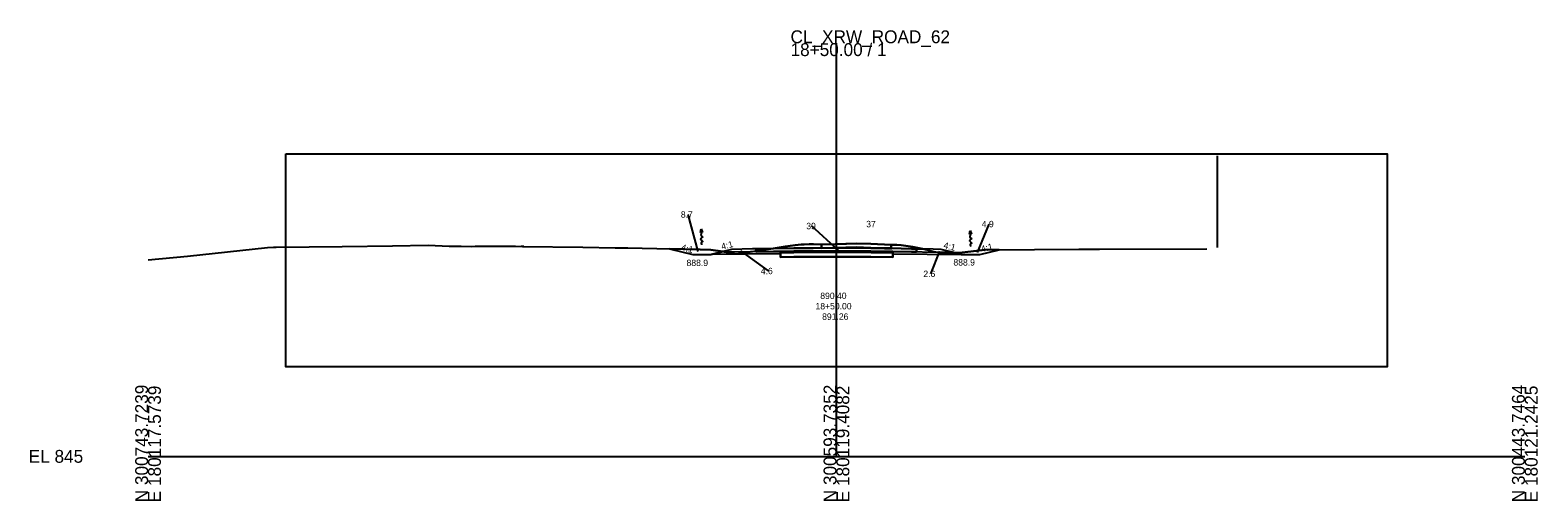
# Model space of a CAD drawing. Extents: x -26 to 180171, y 490 to 300744.
# Drawn here: x -25.7 to 302.8, y 3490.3 to 3592.8 of the extents above; entities that cross this region are included whole.
import ezdxf

# ---------------------------------------------------------------- set-up
doc = ezdxf.new("R2010")
doc.units = 0
for name, color, linetype in [('CM_Corridor_Top_Mesh', 7, 'Continuous'), ('Default', 7, 'Continuous'), ('DR_P_Ditch', 7, 'Continuous'), ('DT_P_Contour_Major', 7, 'Continuous'), ('DT_P_Spot_Elevations', 7, 'Continuous'), ('DT_P_TIN_Hull', 7, 'Continuous'), ('DT_P_Void', 7, 'Continuous'), ('DT_X_Void', 7, 'Continuous'), ('GK_Patterns', 7, 'Continuous'), ('MD_P_Surface_Aggregate_Base', 7, 'Continuous'), ('MD_P_Surface_Asphalt_Concrete_Base', 7, 'Continuous'), ('MD_P_Surface_Asphalt_Concrete_Surface_Course', 7, 'Continuous'), ('MD_P_Surface_Chemically_Stabalized_Subgrade', 7, 'Continuous'), ('PV_P_Saw_Cut_Line', 7, 'Continuous'), ('RD_P_Fence', 7, 'Continuous'), ('RW_P_Const_Limits', 7, 'Continuous'), ('RW_P_Esmt_LA', 7, 'Continuous'), ('RW_X_CL_50', 7, 'Continuous'), ('SC_Scratch1', 7, 'Continuous'), ('SV_X_Control_Cells_Found', 7, 'Continuous'), ('SV_X_Text_Name', 7, 'Continuous'), ('TX_P_1', 7, 'Continuous'), ('XS_X_Ground_Line', 7, 'Continuous')]:
    doc.layers.add(name, color=color, linetype=linetype)

msp = doc.modelspace()

# ---------------------------------------------------------------- linework, layer by layer
at = {"layer": 'CM_Corridor_Top_Mesh'}
for p, q in [((118.69, 3543.96), (122.69, 3543.96)), ((177.25, 3543.96), (181.25, 3543.96))]:
    msp.add_line(p, q, dxfattribs=at)
at = {"layer": 'DR_P_Ditch'}
msp.add_lwpolyline([(167.48, 3545.22), (167.48, 3544.55), (166.36, 3544.58), (161.86, 3544.65), (157.53, 3544.7), (153.32, 3544.73), (149.14, 3544.73), (144.96, 3544.72), (140.71, 3544.68), (136.32, 3544.62), (132.5, 3544.55), (132.5, 3545.22), (136.32, 3545.29), (140.71, 3545.35), (144.96, 3545.38), (149.14, 3545.4), (153.32, 3545.39), (157.53, 3545.37), (161.86, 3545.32), (166.36, 3545.24), (167.48, 3545.22)], dxfattribs=at)
at = {"layer": 'DT_P_Contour_Major'}
for points in [[(132.5, 3544.55), (132.5, 3545.22)], [(167.48, 3544.55), (167.48, 3545.22)], [(167.48, 3544.55), (166.36, 3544.58), (162.28, 3544.64), (162.28, 3543.4), (161.86, 3543.41), (157.53, 3543.44), (153.32, 3543.46), (149.14, 3543.46), (144.96, 3543.45), (140.71, 3543.43), (137.83, 3543.4), (137.83, 3544.64), (136.32, 3544.62), (132.5, 3544.55)]]:
    msp.add_lwpolyline(points, dxfattribs=at)
at = {"layer": 'DT_P_Spot_Elevations'}
msp.add_lwpolyline([(172.81, 3545.06), (171.11, 3545.12), (167.48, 3545.22), (167.48, 3544.55), (166.36, 3544.58), (162.28, 3544.64), (161.86, 3544.65), (157.53, 3544.7), (153.32, 3544.73), (149.14, 3544.73), (144.96, 3544.72), (140.71, 3544.68), (137.83, 3544.64), (136.32, 3544.62), (132.5, 3544.55), (132.5, 3545.22), (131.72, 3545.2), (127.11, 3545.06)], dxfattribs=at)
at = {"layer": 'DT_P_Void'}
msp.add_lwpolyline([(30, 3565.91), (270, 3565.91), (270, 3519.48), (30, 3519.48)], close=True, dxfattribs=at)
at = {"layer": 'DT_X_Void'}
for p, q in [((150, 3500), (150, 3590)), ((0, 3500), (150, 3500)), ((150, 3500), (300, 3500))]:
    msp.add_line(p, q, dxfattribs=at)
at = {"layer": 'GK_Patterns'}
for p, q in [((113.65, 3545.22), (118.69, 3543.96)), ((127.11, 3545.06), (122.69, 3543.96)), ((177.25, 3543.96), (172.81, 3545.06)), ((181.25, 3543.96), (185.46, 3545.01))]:
    msp.add_line(p, q, dxfattribs=at)
at = {"layer": 'MD_P_Surface_Asphalt_Concrete_Base'}
msp.add_lwpolyline([(146.78, 3546.17), (146.78, 3545.32), (149.72, 3545.39), (154.39, 3545.55), (157.5, 3545.43), (161.92, 3545.23), (161.92, 3546.09), (157.5, 3546.28), (154.39, 3546.4), (149.72, 3546.25), (146.78, 3546.17)], dxfattribs=at)
at = {"layer": 'MD_P_Surface_Asphalt_Concrete_Surface_Course'}
for p, q in [((120.35, 3548.78), (120.55, 3549.59)), ((120.78, 3548.79), (120.35, 3548.78)), ((120.55, 3549.59), (120.78, 3548.79)), ((178.97, 3548.42), (179.17, 3549.22)), ((179.4, 3548.43), (178.97, 3548.42)), ((179.17, 3549.22), (179.4, 3548.43))]:
    msp.add_line(p, q, dxfattribs=at)
for points in [[(120.56, 3548.79), (120.56, 3548.76), (120.49, 3548.43), (120.43, 3548.22), (120.8, 3547.8), (120.4, 3547.31), (120.83, 3546.76), (120.61, 3546.64), (120.63, 3546.09)], [(179.18, 3548.42), (179.18, 3548.39), (179.12, 3548.06), (179.05, 3547.85), (179.42, 3547.44), (179.02, 3546.94), (179.45, 3546.39), (179.23, 3546.27), (179.25, 3545.72)]]:
    msp.add_spline(points, degree=3, dxfattribs=at)
at = {"layer": 'MD_P_Surface_Chemically_Stabalized_Subgrade'}
for p, q in [((137.83, 3544.4), (137.83, 3543.4)), ((137.83, 3543.4), (140.71, 3543.43)), ((162.28, 3543.4), (162.28, 3544.4))]:
    msp.add_line(p, q, dxfattribs=at)
for points in [[(162.28, 3544.4), (161.86, 3544.41), (157.53, 3544.44), (153.32, 3544.46), (149.14, 3544.46), (144.96, 3544.45), (140.71, 3544.43), (137.83, 3544.4)], [(140.71, 3543.43), (144.96, 3543.45), (149.14, 3543.46), (153.31, 3543.46), (157.53, 3543.44), (162.28, 3543.4)]]:
    msp.add_lwpolyline(points, dxfattribs=at)
at = {"layer": 'PV_P_Saw_Cut_Line'}
msp.add_lwpolyline([(172.81, 3545.06), (171.11, 3545.12), (167.48, 3545.22), (166.36, 3545.24), (161.86, 3545.32), (157.53, 3545.37), (153.32, 3545.39), (149.14, 3545.4), (144.96, 3545.38), (140.71, 3545.35), (136.32, 3545.29), (132.5, 3545.22), (131.72, 3545.2), (127.11, 3545.06)], dxfattribs=at)
at = {"layer": 'RD_P_Fence'}
msp.add_lwpolyline([(146.78, 3546.17), (146.78, 3545.32), (149.72, 3545.39), (154.39, 3545.55), (157.5, 3545.43), (161.92, 3545.23), (161.92, 3546.09), (157.5, 3546.28), (154.39, 3546.4), (149.72, 3546.25), (146.78, 3546.17)], dxfattribs=at)
at = {"layer": 'RW_P_Const_Limits'}
for points in [[(132.5, 3545.22), (131.72, 3545.2), (127.11, 3545.06)], [(172.81, 3545.06), (171.11, 3545.12), (167.48, 3545.22)]]:
    msp.add_lwpolyline(points, dxfattribs=at)
at = {"layer": 'RW_P_Esmt_LA'}
msp.add_lwpolyline([(146.78, 3546.17), (149.72, 3546.25), (154.39, 3546.4), (157.5, 3546.28), (161.92, 3546.09)], dxfattribs=at)
at = {"layer": 'RW_X_CL_50'}
for points in [[(27.65, 3545.52), (27.35, 3545.52)], [(81.61, 3545.73), (81.31, 3545.73)]]:
    msp.add_lwpolyline(points, dxfattribs=at)
at = {"layer": 'SC_Scratch1'}
msp.add_lwpolyline([(0, 3542.82), (8.6, 3543.64), (26.04, 3545.52), (27.92, 3545.55), (42.32, 3545.7), (53.24, 3545.84), (61.07, 3546), (65.62, 3545.76), (68.23, 3545.75), (70.4, 3545.71), (71.31, 3545.79), (77.06, 3545.78), (80.04, 3545.78), (81.62, 3545.74), (94.74, 3545.56), (101.79, 3545.43), (104.57, 3545.4), (120.33, 3545.08), (122.64, 3544.97), (123.62, 3544.83), (124.26, 3544.78), (128.18, 3544.15), (136.19, 3545.3), (138.83, 3545.7), (141.03, 3545.98), (142.33, 3546.15), (143, 3546.18), (144.03, 3546.24), (145, 3546.22), (146.78, 3546.17), (150, 3546.25), (154.39, 3546.4), (157.5, 3546.28), (161.92, 3546.09), (163.19, 3546.06), (164.1, 3546.04), (166.65, 3545.63), (168.11, 3545.34), (171.22, 3544.66), (172.78, 3544.3), (174.17, 3544.33), (176.72, 3544.3), (179.3, 3544.6), (182.36, 3545), (193.19, 3545.04), (202.81, 3545.16), (207.32, 3545.13), (230.71, 3545.2)], dxfattribs=at)
at = {"layer": 'SV_X_Control_Cells_Found'}
msp.add_line((232.96, 3565.49), (232.96, 3545.49), dxfattribs=at)
at = {"layer": 'SV_X_Text_Name'}
for p, q in [((119.87, 3544.59), (117.72, 3552.69)), ((150.42, 3544.81), (144.58, 3550.18)), ((180.73, 3544.44), (183.27, 3550.6)), ((113.65, 3545.22), (118.69, 3543.96)), ((127.11, 3545.06), (125.31, 3544.61)), ((132.5, 3544.77), (132.5, 3545.22)), ((146.78, 3545.32), (146.78, 3546.17)), ((149.72, 3545.39), (146.78, 3545.32)), ((154.39, 3545.55), (149.72, 3545.39)), ((157.5, 3545.43), (154.39, 3545.55)), ((167.48, 3544.55), (167.48, 3545.22)), ((167.48, 3545.22), (168.84, 3545.18)), ((168.84, 3545.18), (168.11, 3545.34)), ((168.84, 3545.18), (171.22, 3544.66)), ((175.84, 3544.31), (172.81, 3545.06)), ((181.25, 3543.96), (185.46, 3545.01)), ((185.46, 3545.01), (182.36, 3545)), ((118.69, 3543.96), (122.69, 3543.96)), ((122.69, 3543.96), (125.31, 3544.61)), ((125.31, 3544.61), (124.26, 3544.78)), ((125.31, 3544.61), (128.18, 3544.15)), ((128.18, 3544.15), (132.5, 3544.77)), ((129.09, 3544.74), (135.13, 3540.38)), ((132.5, 3544.77), (132.5, 3544.55)), ((172.48, 3544.73), (170.53, 3539.76)), ((175.84, 3544.31), (177.25, 3543.96)), ((177.25, 3543.96), (181.25, 3543.96))]:
    msp.add_line(p, q, dxfattribs=at)
for points in [[(124.26, 3544.78), (123.62, 3544.83), (122.64, 3544.97), (120.33, 3545.08), (113.65, 3545.22)], [(132.5, 3545.22), (131.72, 3545.2), (127.11, 3545.06)], [(146.78, 3546.17), (145, 3546.22), (144.03, 3546.24), (143, 3546.18), (142.33, 3546.15), (141.03, 3545.98), (138.83, 3545.7), (136.19, 3545.3), (132.5, 3544.77)], [(161.92, 3546.09), (161.92, 3545.23), (157.5, 3545.43)], [(168.11, 3545.34), (166.65, 3545.63), (164.1, 3546.04), (163.19, 3546.06), (161.92, 3546.09)], [(172.81, 3545.06), (171.11, 3545.12), (168.84, 3545.18)], [(182.36, 3545), (179.3, 3544.6), (176.72, 3544.3), (175.84, 3544.31)], [(132.5, 3544.55), (136.32, 3544.62), (137.83, 3544.64), (137.83, 3544.4), (140.7, 3544.44), (145.02, 3544.45), (149.14, 3544.5), (153.46, 3544.46)], [(153.46, 3544.46), (157.54, 3544.44), (161.39, 3544.41), (162.28, 3544.4)], [(162.28, 3544.4), (162.28, 3544.64), (166.36, 3544.58), (167.48, 3544.55)], [(171.22, 3544.66), (172.78, 3544.3), (174.17, 3544.33), (175.84, 3544.31)]]:
    msp.add_lwpolyline(points, dxfattribs=at)
at = {"layer": 'TX_P_1'}
for points in [[(27.95, 3545.52), (27.65, 3545.52)], [(81.91, 3545.73), (81.61, 3545.73)]]:
    msp.add_lwpolyline(points, dxfattribs=at)
at = {"layer": 'XS_X_Ground_Line'}
for p, q in [((137.83, 3544.11), (122.69, 3543.96)), ((137.83, 3544.61), (124.77, 3544.48)), ((137.83, 3544.61), (137.83, 3544.11)), ((162.28, 3544.61), (175.16, 3544.48)), ((162.28, 3544.11), (162.28, 3544.61)), ((162.28, 3544.11), (177.25, 3543.96))]:
    msp.add_line(p, q, dxfattribs=at)

# ---------------------------------------------------------------- texts
at = {"layer": 'Default'}
msp.add_text('-', height=0.0001, dxfattribs=at).set_placement((0, 3500))
at = {"layer": 'DT_P_TIN_Hull'}
for s, p in [('890.40', (146.48, 3534.27)), ('18+50.00', (145.44, 3532.01)), ('891.26', (146.88, 3529.74))]:
    msp.add_text(s, height=1.4, dxfattribs=at).set_placement(p)
at = {"layer": 'DT_X_Void'}
for s, p in [('CL_XRW_ROAD_62', (140, 3590)), ('18+50.00 / 1', (140, 3587.2)), ('EL 845', (-26, 3498.6))]:
    msp.add_text(s, height=2.8, dxfattribs=at).set_placement(p)
for s, p in [('N 300743.7239', (0, 3490)), ('N 300593.7352', (150, 3490)), ('N 300443.7464', (300, 3490)), ('E 180117.5739', (2.8, 3490)), ('E 180119.4082', (152.8, 3490)), ('E 180121.2425', (302.8, 3490))]:
    msp.add_text(s, height=2.8, rotation=90, dxfattribs=at).set_placement(p)
at = {"layer": 'MD_P_Surface_Aggregate_Base'}
for rotation, p in [(345.9638, (116.05, 3544.9)), (14.0362, (125.08, 3544.99)), (345.9638, (173.23, 3545.37)), (14.0362, (181.66, 3544.45))]:
    msp.add_text('4:1', height=1.4, rotation=rotation, dxfattribs=at).set_placement(p)
for p in [(117.34, 3541.45), (175.49, 3541.56)]:
    msp.add_text('888.9', height=1.4, dxfattribs=at).set_placement(p)
at = {"layer": 'SV_X_Text_Name'}
for s, p in [('8.7', (116.1, 3551.99)), ('39', (143.43, 3549.48)), ('37', (156.49, 3549.9)), ('4.9', (181.67, 3549.9)), ('4.6', (133.52, 3539.68)), ('2.6', (168.94, 3539.06))]:
    msp.add_text(s, height=1.4, dxfattribs=at).set_placement(p)

doc.saveas('drawing.dxf')
